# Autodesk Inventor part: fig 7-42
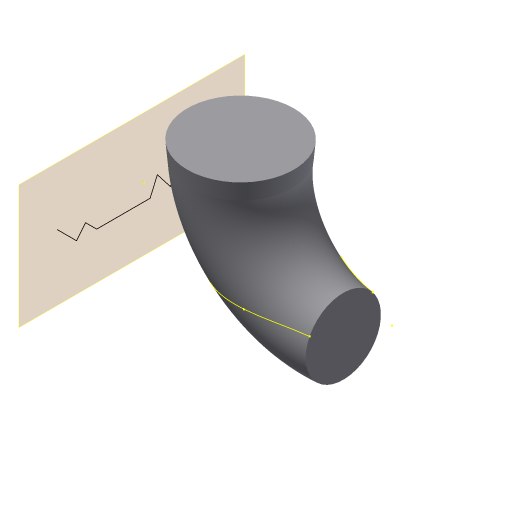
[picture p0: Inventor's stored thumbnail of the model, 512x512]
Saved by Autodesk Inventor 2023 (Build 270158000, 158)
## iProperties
Created: 2011-07
Part Number: fig 7-42
Material: Generic
Document SubType Name: Modeling
Designer: CadCim
Density: 1 g/cm^3
Appearance: Default
Author: CadCim
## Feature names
1. Sweep1
## Parameters: d0 = 5 deg, d1 = -14.75 mm, d2 = 0
